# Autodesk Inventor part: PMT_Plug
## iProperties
Shininess: 64.0
Length Units: 11272
Angle Units: 11279
Time Units: 11290
Mass Units: 11286
Length Display Precision: 3
Angle Display Precision: 2
Compacted: True
Part Number: PMT_Plug
Document SubType Name: Modeling
Created: 2005-11
Designer: John Blackburn
Material: Aluminum-6061
Manufacturer: Standard
Standards Organization: Custom
Density: 0.0
Volumn: 0.0
Area: 0.0
PropertySet Name: Model Information
Control State: 0
Master: False
Checked Out: False
Author: John Blackburn
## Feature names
1. Revolution1
2. Chamfer1
3. Fillet1
